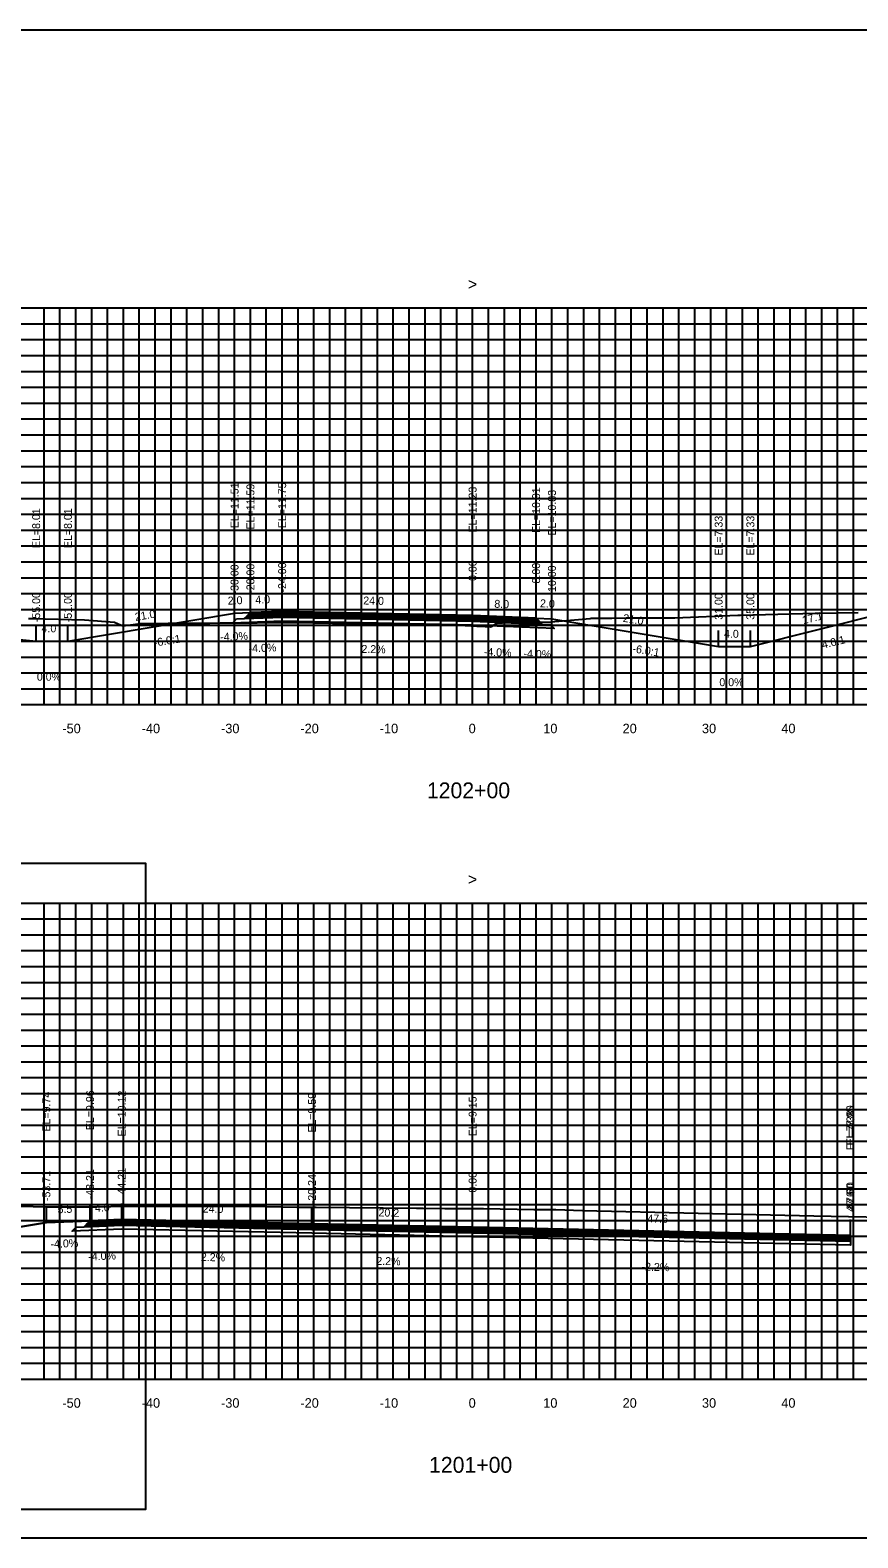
# Model space of a CAD drawing. Extents: x 1797305 to 1804485, y 245831 to 250849.
# Drawn here: x 1802235.2 to 1802339.5, y 250079.4 to 250269.4 of the extents above; entities that cross this region are included whole.
import ezdxf

# ---------------------------------------------------------------- set-up
doc = ezdxf.new("R2010")
doc.units = 0
for name, color, linetype in [('1', 7, 'Continuous'), ('10', 7, 'Continuous'), ('29', 7, 'Continuous'), ('ALIGN-CARP', 7, 'Continuous'), ('BASE', 7, 'Continuous'), ('CL-CNST', 7, 'Continuous'), ('Level 31', 7, 'Continuous'), ('Level 62', 7, 'Continuous'), ('LIMT-CSLINE', 7, 'Continuous'), ('M-ROADS', 7, 'Continuous'), ('SURVEY - DRAINAGE - Area Shapes', 7, 'Continuous'), ('SURVEY - DRAINAGE - Bridge Hydraulic Data - Points - Locators', 7, 'Continuous')]:
    doc.layers.add(name, color=color, linetype=linetype)

msp = doc.modelspace()

# ---------------------------------------------------------------- linework, layer by layer
for p, q in [((1802261, 250195.95), (1802261, 250197.95)), ((1802263, 250196.03), (1802263, 250198.03)), ((1802267, 250196.19), (1802267, 250198.19)), ((1802291, 250195.66), (1802291, 250197.66)), ((1802299, 250195.34), (1802299, 250197.34)), ((1802301, 250195.26), (1802301, 250197.26)), ((1802236, 250192.45), (1802236, 250194.45)), ((1802240, 250192.45), (1802240, 250194.45)), ((1802322, 250191.76), (1802322, 250193.76)), ((1802326, 250191.76), (1802326, 250193.76)), ((1802237.29, 250119.17), (1802237.29, 250121.17)), ((1802242.79, 250119.39), (1802242.79, 250121.39)), ((1802246.79, 250119.55), (1802246.79, 250121.55)), ((1802270.76, 250119.02), (1802270.76, 250121.02)), ((1802291, 250118.58), (1802291, 250120.58)), ((1802338.6, 250117.53), (1802338.6, 250119.53)), ((1802338.61, 250117.38), (1802338.61, 250119.38)), ((1802338.61, 250116.81), (1802338.61, 250118.81))]:
    msp.add_line(p, q)
msp.add_lwpolyline([(1802141, 250079.43), (1802441, 250079.43), (1802441, 250269.43), (1802141, 250269.43)], close=True)
at = {"layer": '1'}
msp.add_line((1802237.29, 250119.17), (1802211.14, 250114.81), dxfattribs=at)
msp.add_lwpolyline([(1802177.03, 250164.46), (1802249.79, 250164.46), (1802249.79, 250082.99), (1802177.03, 250082.99)], close=True, dxfattribs=at)
at = {"layer": '29'}
for p, q in [((1802141, 250234.43), (1802441, 250234.43)), ((1802237, 250184.43), (1802237, 250234.43)), ((1802239, 250184.43), (1802239, 250234.43)), ((1802241, 250184.43), (1802241, 250234.43)), ((1802243, 250184.43), (1802243, 250234.43)), ((1802245, 250184.43), (1802245, 250234.43)), ((1802247, 250184.43), (1802247, 250234.43)), ((1802249, 250184.43), (1802249, 250234.43)), ((1802251, 250184.43), (1802251, 250234.43)), ((1802253, 250184.43), (1802253, 250234.43)), ((1802255, 250184.43), (1802255, 250234.43)), ((1802257, 250184.43), (1802257, 250234.43)), ((1802259, 250184.43), (1802259, 250234.43)), ((1802261, 250184.43), (1802261, 250234.43)), ((1802263, 250184.43), (1802263, 250234.43)), ((1802265, 250184.43), (1802265, 250234.43)), ((1802267, 250184.43), (1802267, 250234.43)), ((1802269, 250184.43), (1802269, 250234.43)), ((1802271, 250184.43), (1802271, 250234.43)), ((1802273, 250184.43), (1802273, 250234.43)), ((1802275, 250184.43), (1802275, 250234.43)), ((1802277, 250184.43), (1802277, 250234.43)), ((1802279, 250184.43), (1802279, 250234.43)), ((1802281, 250184.43), (1802281, 250234.43)), ((1802283, 250184.43), (1802283, 250234.43)), ((1802285, 250184.43), (1802285, 250234.43)), ((1802287, 250184.43), (1802287, 250234.43)), ((1802289, 250184.43), (1802289, 250234.43)), ((1802291, 250184.43), (1802291, 250234.43)), ((1802293, 250184.43), (1802293, 250234.43)), ((1802295, 250184.43), (1802295, 250234.43)), ((1802297, 250184.43), (1802297, 250234.43)), ((1802299, 250184.43), (1802299, 250234.43)), ((1802301, 250184.43), (1802301, 250234.43)), ((1802303, 250184.43), (1802303, 250234.43)), ((1802305, 250184.43), (1802305, 250234.43)), ((1802307, 250184.43), (1802307, 250234.43)), ((1802309, 250184.43), (1802309, 250234.43)), ((1802311, 250184.43), (1802311, 250234.43)), ((1802313, 250184.43), (1802313, 250234.43)), ((1802315, 250184.43), (1802315, 250234.43)), ((1802317, 250184.43), (1802317, 250234.43)), ((1802319, 250184.43), (1802319, 250234.43)), ((1802321, 250184.43), (1802321, 250234.43)), ((1802323, 250184.43), (1802323, 250234.43)), ((1802325, 250184.43), (1802325, 250234.43)), ((1802327, 250184.43), (1802327, 250234.43)), ((1802329, 250184.43), (1802329, 250234.43)), ((1802331, 250184.43), (1802331, 250234.43)), ((1802333, 250184.43), (1802333, 250234.43)), ((1802335, 250184.43), (1802335, 250234.43)), ((1802337, 250184.43), (1802337, 250234.43)), ((1802339, 250184.43), (1802339, 250234.43)), ((1802141, 250232.43), (1802441, 250232.43)), ((1802141, 250230.43), (1802441, 250230.43)), ((1802141, 250228.43), (1802441, 250228.43)), ((1802141, 250226.43), (1802441, 250226.43)), ((1802141, 250224.43), (1802441, 250224.43)), ((1802141, 250222.43), (1802441, 250222.43)), ((1802141, 250220.43), (1802441, 250220.43)), ((1802141, 250218.43), (1802441, 250218.43)), ((1802141, 250216.43), (1802441, 250216.43)), ((1802141, 250214.43), (1802441, 250214.43)), ((1802141, 250212.43), (1802441, 250212.43)), ((1802141, 250210.43), (1802441, 250210.43)), ((1802141, 250208.43), (1802441, 250208.43)), ((1802141, 250206.43), (1802441, 250206.43)), ((1802141, 250204.43), (1802441, 250204.43)), ((1802141, 250202.43), (1802441, 250202.43)), ((1802141, 250200.43), (1802441, 250200.43)), ((1802141, 250198.43), (1802441, 250198.43)), ((1802141, 250196.43), (1802441, 250196.43)), ((1802141, 250194.43), (1802441, 250194.43)), ((1802141, 250192.43), (1802441, 250192.43)), ((1802141, 250190.43), (1802441, 250190.43)), ((1802141, 250188.43), (1802441, 250188.43)), ((1802141, 250186.43), (1802441, 250186.43)), ((1802141, 250184.43), (1802441, 250184.43)), ((1802141, 250159.43), (1802441, 250159.43)), ((1802237, 250099.43), (1802237, 250159.43)), ((1802239, 250099.43), (1802239, 250159.43)), ((1802241, 250099.43), (1802241, 250159.43)), ((1802243, 250099.43), (1802243, 250159.43)), ((1802245, 250099.43), (1802245, 250159.43)), ((1802247, 250099.43), (1802247, 250159.43)), ((1802249, 250099.43), (1802249, 250159.43)), ((1802251, 250099.43), (1802251, 250159.43)), ((1802253, 250099.43), (1802253, 250159.43)), ((1802255, 250099.43), (1802255, 250159.43)), ((1802257, 250099.43), (1802257, 250159.43)), ((1802259, 250099.43), (1802259, 250159.43)), ((1802261, 250099.43), (1802261, 250159.43)), ((1802263, 250099.43), (1802263, 250159.43)), ((1802265, 250099.43), (1802265, 250159.43)), ((1802267, 250099.43), (1802267, 250159.43)), ((1802269, 250099.43), (1802269, 250159.43)), ((1802271, 250099.43), (1802271, 250159.43)), ((1802273, 250099.43), (1802273, 250159.43)), ((1802275, 250099.43), (1802275, 250159.43)), ((1802277, 250099.43), (1802277, 250159.43)), ((1802279, 250099.43), (1802279, 250159.43)), ((1802281, 250099.43), (1802281, 250159.43)), ((1802283, 250099.43), (1802283, 250159.43)), ((1802285, 250099.43), (1802285, 250159.43)), ((1802287, 250099.43), (1802287, 250159.43)), ((1802289, 250099.43), (1802289, 250159.43)), ((1802291, 250099.43), (1802291, 250159.43)), ((1802293, 250099.43), (1802293, 250159.43)), ((1802295, 250099.43), (1802295, 250159.43)), ((1802297, 250099.43), (1802297, 250159.43)), ((1802299, 250099.43), (1802299, 250159.43)), ((1802301, 250099.43), (1802301, 250159.43)), ((1802303, 250099.43), (1802303, 250159.43)), ((1802305, 250099.43), (1802305, 250159.43)), ((1802307, 250099.43), (1802307, 250159.43)), ((1802309, 250099.43), (1802309, 250159.43)), ((1802311, 250099.43), (1802311, 250159.43)), ((1802313, 250099.43), (1802313, 250159.43)), ((1802315, 250099.43), (1802315, 250159.43)), ((1802317, 250099.43), (1802317, 250159.43)), ((1802319, 250099.43), (1802319, 250159.43)), ((1802321, 250099.43), (1802321, 250159.43)), ((1802323, 250099.43), (1802323, 250159.43)), ((1802325, 250099.43), (1802325, 250159.43)), ((1802327, 250099.43), (1802327, 250159.43)), ((1802329, 250099.43), (1802329, 250159.43)), ((1802331, 250099.43), (1802331, 250159.43)), ((1802333, 250099.43), (1802333, 250159.43)), ((1802335, 250099.43), (1802335, 250159.43)), ((1802337, 250099.43), (1802337, 250159.43)), ((1802339, 250099.43), (1802339, 250159.43)), ((1802141, 250157.43), (1802441, 250157.43)), ((1802141, 250155.43), (1802441, 250155.43)), ((1802141, 250153.43), (1802441, 250153.43)), ((1802141, 250151.43), (1802441, 250151.43)), ((1802141, 250149.43), (1802441, 250149.43)), ((1802141, 250147.43), (1802441, 250147.43)), ((1802141, 250145.43), (1802441, 250145.43)), ((1802141, 250143.43), (1802441, 250143.43)), ((1802141, 250141.43), (1802441, 250141.43)), ((1802141, 250139.43), (1802441, 250139.43)), ((1802141, 250137.43), (1802441, 250137.43)), ((1802141, 250135.43), (1802441, 250135.43)), ((1802141, 250133.43), (1802441, 250133.43)), ((1802141, 250131.43), (1802441, 250131.43)), ((1802141, 250129.43), (1802441, 250129.43)), ((1802141, 250127.43), (1802441, 250127.43)), ((1802141, 250125.43), (1802441, 250125.43)), ((1802141, 250123.43), (1802441, 250123.43)), ((1802141, 250121.43), (1802441, 250121.43)), ((1802141, 250119.43), (1802441, 250119.43)), ((1802141, 250117.43), (1802441, 250117.43)), ((1802141, 250115.43), (1802441, 250115.43)), ((1802141, 250113.43), (1802441, 250113.43)), ((1802141, 250111.43), (1802441, 250111.43)), ((1802141, 250109.43), (1802441, 250109.43)), ((1802141, 250107.43), (1802441, 250107.43)), ((1802141, 250105.43), (1802441, 250105.43)), ((1802141, 250103.43), (1802441, 250103.43)), ((1802141, 250101.43), (1802441, 250101.43)), ((1802141, 250099.43), (1802441, 250099.43))]:
    msp.add_line(p, q, dxfattribs=at)
at = {"layer": 'ALIGN-CARP'}
for points in [[(1802261.25, 250195.24), (1802262.25, 250195.28), (1802267, 250195.47), (1802291, 250194.94), (1802299.75, 250194.59), (1802300.75, 250194.55), (1802301.27, 250194.03), (1802291, 250194.44), (1802267, 250194.97), (1802260.73, 250194.71)], [(1802241.04, 250118.6), (1802242.04, 250118.64), (1802246.79, 250118.83), (1802270.76, 250118.31), (1802291, 250117.86), (1802338.61, 250116.81), (1802338.61, 250116.31), (1802291, 250117.36), (1802270.76, 250117.81), (1802246.79, 250118.33), (1802240.52, 250118.08)]]:
    msp.add_lwpolyline(points, close=True, dxfattribs=at)
at = {"layer": 'CL-CNST'}
for points in [[(1802201.65, 250195.88), (1802236, 250192.45), (1802240, 250192.45), (1802261, 250195.95), (1802263, 250196.03), (1802267, 250196.19), (1802291, 250195.66), (1802299, 250195.34), (1802301, 250195.26), (1802322, 250191.76), (1802326, 250191.76), (1802343.07, 250196.03)], [(1802189.49, 250121.37), (1802212.29, 250115.67), (1802216.29, 250115.67), (1802237.29, 250119.17), (1802242.79, 250119.39), (1802246.79, 250119.55), (1802270.76, 250119.02), (1802291, 250118.58), (1802338.6, 250117.53), (1802338.61, 250117.38), (1802338.61, 250116.81)]]:
    msp.add_lwpolyline(points, dxfattribs=at)
at = {"layer": 'Level 31'}
for p, q in [((1802141, 250184.43), (1802441, 250184.43)), ((1802241, 250184.37), (1802241, 250184.43)), ((1802251, 250184.37), (1802251, 250184.43)), ((1802261, 250184.37), (1802261, 250184.43)), ((1802271, 250184.37), (1802271, 250184.43)), ((1802281, 250184.37), (1802281, 250184.43)), ((1802291, 250184.37), (1802291, 250184.43)), ((1802301, 250184.37), (1802301, 250184.43)), ((1802311, 250184.37), (1802311, 250184.43)), ((1802321, 250184.37), (1802321, 250184.43)), ((1802331, 250184.37), (1802331, 250184.43)), ((1802141, 250099.43), (1802441, 250099.43)), ((1802241, 250099.37), (1802241, 250099.43)), ((1802251, 250099.37), (1802251, 250099.43)), ((1802261, 250099.37), (1802261, 250099.43)), ((1802271, 250099.37), (1802271, 250099.43)), ((1802281, 250099.37), (1802281, 250099.43)), ((1802291, 250099.37), (1802291, 250099.43)), ((1802301, 250099.37), (1802301, 250099.43)), ((1802311, 250099.37), (1802311, 250099.43)), ((1802321, 250099.37), (1802321, 250099.43)), ((1802331, 250099.37), (1802331, 250099.43))]:
    msp.add_line(p, q, dxfattribs=at)
at = {"layer": 'Level 62'}
for points in [[(1802299.36, 250194.98), (1802299.16, 250195.18), (1802291, 250195.51), (1802267, 250196.04), (1802262.85, 250195.87), (1802262.65, 250195.67), (1802267, 250195.85), (1802291, 250195.32)], [(1802338.61, 250117.38), (1802291, 250118.43), (1802270.76, 250118.87), (1802246.79, 250119.4), (1802242.63, 250119.23), (1802242.44, 250119.04), (1802246.79, 250119.21), (1802270.76, 250118.68), (1802291, 250118.24), (1802338.61, 250117.19)]]:
    msp.add_lwpolyline(points, close=True, dxfattribs=at)
at = {"layer": 'M-ROADS'}
for points in [[(1802235.04, 250195.3), (1802235.27, 250195.3), (1802235.51, 250195.3), (1802242.08, 250195.12), (1802245.86, 250194.81), (1802246.32, 250194.61), (1802246.93, 250194.36), (1802248.86, 250194.62), (1802248.99, 250194.63), (1802249.13, 250194.64), (1802249.18, 250194.64), (1802249.94, 250194.65), (1802250.04, 250194.65), (1802252.25, 250194.67), (1802252.65, 250194.68), (1802254.57, 250194.69), (1802255.27, 250194.7), (1802256.88, 250194.71), (1802257.89, 250194.72), (1802259.2, 250194.73), (1802260.5, 250194.74), (1802261.52, 250194.74), (1802263.12, 250194.75), (1802263.83, 250194.76), (1802265.74, 250194.77), (1802266.15, 250194.77), (1802268.35, 250194.78), (1802268.47, 250194.78), (1802269.4, 250194.78), (1802270.88, 250194.76), (1802271.1, 250194.76), (1802273.35, 250194.72), (1802273.93, 250194.71), (1802275.83, 250194.68), (1802276.76, 250194.66), (1802278.3, 250194.64), (1802279.6, 250194.62), (1802280.77, 250194.6), (1802282.44, 250194.57), (1802283.24, 250194.56), (1802285.28, 250194.53), (1802285.71, 250194.52), (1802288.11, 250194.48), (1802288.19, 250194.48), (1802288.67, 250194.47), (1802289.26, 250194.44), (1802290.83, 250194.37), (1802291.52, 250194.33), (1802291.9, 250194.32), (1802293.25, 250194.25), (1802293.37, 250194.3), (1802294.15, 250194.73), (1802294.77, 250194.74), (1802300.86, 250194.86), (1802305.83, 250195.3), (1802305.95, 250195.34), (1802306.62, 250195.33), (1802306.7, 250195.33), (1802308.12, 250195.33), (1802308.19, 250195.33), (1802308.54, 250195.33), (1802310.34, 250195.38), (1802310.77, 250195.39), (1802316.36, 250195.37), (1802316.49, 250195.37), (1802324.4, 250195.72), (1802324.76, 250195.72), (1802334.16, 250195.97), (1802334.54, 250195.97), (1802339.57, 250196.03)], [(1802228.83, 250121.22), (1802235.64, 250121.18), (1802237.4, 250121.14), (1802237.55, 250121.14), (1802240.66, 250121.13), (1802243.65, 250121.16), (1802245.43, 250121.17), (1802249.93, 250121.24), (1802251.41, 250121.23), (1802253.92, 250121.22), (1802256.82, 250121.23), (1802259.06, 250121.23), (1802263.71, 250121.21), (1802264.99, 250121.19), (1802268.87, 250121.12), (1802271.29, 250121.12), (1802283.92, 250120.98), (1802284.78, 250120.97), (1802287.51, 250120.95), (1802288.36, 250120.95), (1802288.59, 250120.95), (1802289.54, 250120.95), (1802291.82, 250120.94), (1802292.37, 250120.94), (1802298.71, 250120.83), (1802300.84, 250120.83), (1802301.5, 250120.83), (1802304.86, 250120.7), (1802333.99, 250120.02), (1802347.16, 250119.76)]]:
    msp.add_lwpolyline(points, dxfattribs=at)
at = {"layer": 'SURVEY - DRAINAGE - Area Shapes'}
for points in [[(1802299.16, 250195.18), (1802299, 250195.34), (1802291, 250195.66), (1802267, 250196.19), (1802263, 250196.03), (1802262.85, 250195.87), (1802267, 250196.04), (1802291, 250195.51)], [(1802338.6, 250117.53), (1802291, 250118.58), (1802270.76, 250119.02), (1802246.79, 250119.55), (1802242.79, 250119.39), (1802242.63, 250119.23), (1802246.79, 250119.4), (1802270.76, 250118.87), (1802291, 250118.43), (1802338.61, 250117.38)]]:
    msp.add_lwpolyline(points, close=True, dxfattribs=at)
at = {"layer": 'SURVEY - DRAINAGE - Bridge Hydraulic Data - Points - Locators'}
for points in [[(1802267, 250195.85), (1802291, 250195.32), (1802299.36, 250194.98), (1802299.55, 250194.79), (1802291, 250195.13), (1802267, 250195.66), (1802262.45, 250195.47), (1802262.65, 250195.67)], [(1802267, 250195.66), (1802291, 250195.13), (1802299.55, 250194.79), (1802299.75, 250194.59), (1802291, 250194.94), (1802267, 250195.47), (1802262.25, 250195.28), (1802262.45, 250195.47)], [(1802246.79, 250119.02), (1802270.76, 250118.49), (1802291, 250118.05), (1802338.61, 250117.01), (1802338.61, 250116.81), (1802291, 250117.86), (1802270.76, 250118.31), (1802246.79, 250118.83), (1802242.04, 250118.64), (1802242.24, 250118.84)], [(1802246.79, 250119.21), (1802270.76, 250118.68), (1802291, 250118.24), (1802338.61, 250117.19), (1802338.61, 250117.01), (1802291, 250118.05), (1802270.76, 250118.49), (1802246.79, 250119.02), (1802242.24, 250118.84), (1802242.44, 250119.04)]]:
    msp.add_lwpolyline(points, close=True, dxfattribs=at)

# ---------------------------------------------------------------- texts
for s, rotation, p in [('-6.0:1', 9.4623, (1802250.91, 250191.73)), ('4.0:1', 14.0362, (1802335.14, 250191.47)), ('-6.0:1', 350.5377, (1802311.09, 250191.04))]:
    msp.add_text(s, height=1, rotation=rotation).set_placement(p)
at = {"layer": '1'}
for s, p in [('1202+00', (1802285.24, 250172.63)), ('1201+00', (1802285.51, 250087.63))]:
    msp.add_text(s, height=2, dxfattribs=at).set_placement(p)
at = {"layer": '10'}
for s, p in [('-50', (1802239.3, 250180.83)), ('-40', (1802249.3, 250180.83)), ('-30', (1802259.3, 250180.83)), ('-20', (1802269.3, 250180.83)), ('-10', (1802279.3, 250180.83)), ('0', (1802290.5, 250180.83)), ('10', (1802299.9, 250180.83)), ('20', (1802309.9, 250180.83)), ('30', (1802319.9, 250180.83)), ('40', (1802329.9, 250180.83)), ('-50', (1802239.3, 250095.83)), ('-40', (1802249.3, 250095.83)), ('-30', (1802259.3, 250095.83)), ('-20', (1802269.3, 250095.83)), ('-10', (1802279.3, 250095.83)), ('0', (1802290.5, 250095.83)), ('10', (1802299.9, 250095.83)), ('20', (1802309.9, 250095.83)), ('30', (1802319.9, 250095.83)), ('40', (1802329.9, 250095.83))]:
    msp.add_text(s, height=1.2, dxfattribs=at).set_placement(p)
at = {"layer": 'BASE'}
for s, rotation, p in [('2.0', 2.2906, (1802260.16, 250197.03)), ('4.0', 2.2906, (1802263.64, 250197.15)), ('24.0', 358.7397, (1802277.21, 250197.06)), ('2.0', 357.7094, (1802299.48, 250196.71)), ('21.0', 9.4623, (1802248.53, 250194.98)), ('8.0', 357.7094, (1802293.72, 250196.65)), ('21.0', 350.5377, (1802309.89, 250194.89)), ('17.1', 14.0362, (1802332.67, 250194.56)), ('-4.0%', 2.2906, (1802259.21, 250192.47)), ('-4.0%', 2.2906, (1802262.79, 250191.01)), ('2.2%', 358.7397, (1802276.98, 250190.96)), ('-4.0%', 357.7094, (1802292.39, 250190.6)), ('-4.0%', 357.7094, (1802297.39, 250190.4)), ('5.5', 2.2906, (1802238.71, 250120.33)), ('4.0', 2.2906, (1802243.42, 250120.52)), ('24.0', 358.7397, (1802256.98, 250120.43)), ('20.2', 358.7397, (1802279.13, 250119.94)), ('47.6', 358.7397, (1802313.02, 250119.19)), ('-4.0%', 2.2906, (1802237.83, 250115.96)), ('-4.0%', 2.2906, (1802242.58, 250114.38)), ('2.2%', 358.7397, (1802256.75, 250114.33)), ('2.2%', 358.7397, (1802278.86, 250113.84)), ('-2.2%', 358.7397, (1802312.28, 250113.11))]:
    msp.add_text(s, height=1, rotation=rotation, dxfattribs=at).set_placement(p)
for s, p in [('4.0', (1802236.68, 250193.55)), ('4.0', (1802322.68, 250192.86)), ('0.0%', (1802236.09, 250187.45)), ('0.0%', (1802322.09, 250186.76))]:
    msp.add_text(s, height=1, dxfattribs=at).set_placement(p)
at = {"layer": 'Level 31'}
for p in [(1802290.39, 250236.68), (1802290.39, 250161.68)]:
    msp.add_text('>', height=1.5, dxfattribs=at).set_placement(p)
at = {"layer": 'LIMT-CSLINE'}
for s, p in [('EL=11.51', (1802261.5, 250206.67)), ('EL=11.59', (1802263.5, 250206.5)), ('EL=11.75', (1802267.5, 250206.66)), ('EL=11.23', (1802291.5, 250206.13)), ('EL=10.91', (1802299.5, 250206.06)), ('EL=10.83', (1802301.5, 250205.73)), ('EL=8.01', (1802236.5, 250204.16)), ('EL=8.01', (1802240.5, 250204.16)), ('EL=7.33', (1802322.5, 250203.22)), ('EL=7.33', (1802326.5, 250203.22)), ('-30.00', (1802261.5, 250198.32)), ('-28.00', (1802263.5, 250198.4)), ('-24.00', (1802267.5, 250198.56)), ('0.00', (1802291.5, 250200.02)), ('8.00', (1802299.5, 250199.7)), ('10.00', (1802301.5, 250198.63)), ('-55.00', (1802236.5, 250194.82)), ('-51.00', (1802240.5, 250194.82)), ('31.00', (1802322.5, 250195.13)), ('35.00', (1802326.5, 250195.13)), ('EL=9.74', (1802237.79, 250130.63)), ('EL=9.96', (1802243.29, 250130.81)), ('EL=10.12', (1802247.29, 250130.02)), ('EL=9.59', (1802271.26, 250130.49)), ('EL=9.15', (1802291.5, 250130.04)), ('EL=8.10', (1802339.1, 250128.92)), ('EL=7.95', (1802339.11, 250128.85)), ('EL=7.38', (1802339.11, 250128.28)), ('-53.71', (1802237.79, 250121.88)), ('-48.21', (1802243.29, 250122.1)), ('-44.21', (1802247.29, 250122.26)), ('-20.24', (1802271.26, 250121.48)), ('0.00', (1802291.5, 250122.94)), ('47.60', (1802339.1, 250120.9)), ('47.60', (1802339.11, 250120.75)), ('47.61', (1802339.11, 250120.52))]:
    msp.add_text(s, height=1, rotation=90, dxfattribs=at).set_placement(p)

doc.saveas('drawing.dxf')
